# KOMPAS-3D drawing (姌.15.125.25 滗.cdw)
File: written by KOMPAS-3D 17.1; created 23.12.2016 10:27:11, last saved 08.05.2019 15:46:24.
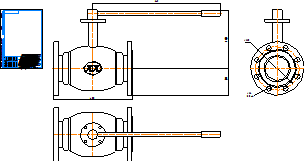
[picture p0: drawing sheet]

Sheet 1: A4, portrait

Title block, sheet 1: name: КШ.15.125.25 фф; material: Внимание! Данный продукт является объектом авторского права ООО «Торговый Дом АДЛ». / Запрещается изменение, копирование, распространение / (в том числе путем копирования на другие сайты и ресурсы в Интернете) / или любое иное использование информации и объектов без предварительного / согласия правообладателя (ООО «Торговый Дом АДЛ»).; sheets: 1; organisation: ООО "Торговый дом АДЛ"; sheet format: A4; stored path: C:\Users\tra\Desktop\2д чертежи\Шаровые краны БИВАЛ\КШ_Бивал_серия_14_15\KOMPAS_2D\КШ.15.125.25 фф.cdw

Views: Вид 1, Проекционный вид 2, Проекционный вид 3
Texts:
  Klimkovich
  ADL
Dimensions and other numbers on the sheet: 400; 645; 291,6; 135; 220; 26; 8 Отв.; 1:1; 1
